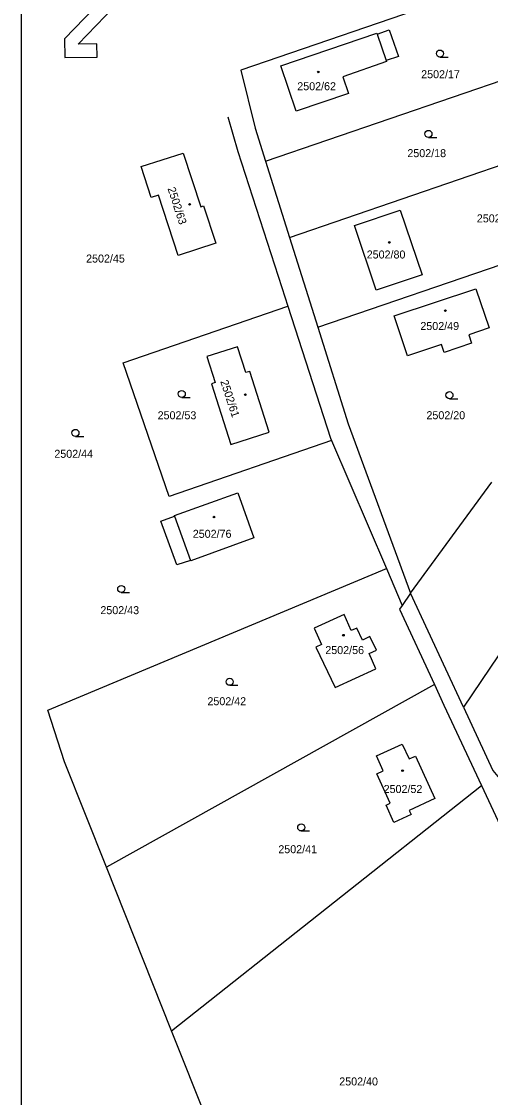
# Model space of a CAD drawing. Extents: x -558358 to -557517, y -1073785 to -1073189.
# Drawn here: x -558357.5 to -558258, y -1073555.9 to -1073327.3 of the extents above; entities that cross this region are included whole.
import ezdxf

# ---------------------------------------------------------------- set-up
doc = ezdxf.new("R2010")
doc.units = 0
for name, color, linetype in [('Hranice parcel', 7, 'Continuous'), ('Parcelní čísla', 7, 'Continuous'), ('Vnitřní kresba', 7, 'Continuous'), ('Vrstva 1', 7, 'Continuous'), ('Značky budov', 7, 'Continuous'), ('Značky kultur', 7, 'Continuous')]:
    doc.layers.add(name, color=color, linetype=linetype)

msp = doc.modelspace()

# ---------------------------------------------------------------- linework, layer by layer
at = {"layer": 'Hranice parcel'}
for p, q in [((-558245.27, -1073315.03), (-558311.02, -1073337.58)), ((-558305.76, -1073356.92), (-558240.15, -1073334.41)), ((-558300.65, -1073373.14), (-558235.73, -1073350.87)), ((-558305.76, -1073356.92), (-558300.65, -1073373.14)), ((-558294.64, -1073392.22), (-558230.35, -1073370.17)), ((-558300.65, -1073373.14), (-558294.64, -1073392.22)), ((-558302.31, -1073383.75), (-558301.02, -1073387.75)), ((-558335.97, -1073399.79), (-558301.02, -1073387.75)), ((-558294.64, -1073392.22), (-558288.18, -1073412.71)), ((-558326.19, -1073428.15), (-558335.97, -1073399.79)), ((-558288.18, -1073412.71), (-558274.97, -1073448.74)), ((-558291.74, -1073416.28), (-558326.19, -1073428.15)), ((-558291.74, -1073416.28), (-558280.07, -1073443.5)), ((-558274.97, -1073448.74), (-558257.7, -1073425.14)), ((-558351.92, -1073473.58), (-558280.07, -1073443.5)), ((-558280.07, -1073443.5), (-558276.72, -1073451.31)), ((-558274.97, -1073448.74), (-558276.72, -1073451.31)), ((-558263.73, -1073472.95), (-558274.97, -1073448.74)), ((-558269.87, -1073468.15), (-558339.52, -1073506.95)), ((-558325.69, -1073541.72), (-558259.89, -1073489.61)), ((-558325.69, -1073541.72), (-558339.52, -1073506.95)), ((-558314.35, -1073570.26), (-558325.69, -1073541.72))]:
    msp.add_line(p, q, dxfattribs=at)
for points in [[(-558302.49, -1073336.69), (-558282.13, -1073329.71), (-558282.06, -1073329.92), (-558279.49, -1073329.04), (-558277.55, -1073334.7), (-558280.12, -1073335.56), (-558280.04, -1073335.79), (-558289.36, -1073338.99), (-558288.15, -1073342.54), (-558299.21, -1073346.34), (-558302.49, -1073336.69)], [(-558311.02, -1073337.58), (-558307.96, -1073349.92), (-558305.76, -1073356.92)], [(-558313.78, -1073347.52), (-558311.65, -1073354.86), (-558302.31, -1073383.75)], [(-558329.99, -1073364.63), (-558332.12, -1073358.09), (-558323.21, -1073355.2), (-558319.51, -1073366.6), (-558318.91, -1073366.43), (-558316.33, -1073374.39), (-558324.28, -1073376.97), (-558328.43, -1073364.14), (-558329.99, -1073364.63)], [(-558282.25, -1073384.34), (-558286.86, -1073370.59), (-558277.14, -1073367.32), (-558272.5, -1073381.07), (-558282.25, -1073384.34)], [(-558278.42, -1073389.81), (-558261.13, -1073384.05), (-558258.31, -1073392.37), (-558262.58, -1073393.82), (-558262, -1073395.6), (-558267.81, -1073397.55), (-558268.37, -1073395.87), (-558275.59, -1073398.26), (-558278.42, -1073389.81)], [(-558301.02, -1073387.75), (-558291.95, -1073415.8), (-558291.74, -1073416.28)], [(-558309.9, -1073401.85), (-558311.67, -1073396.36), (-558318.22, -1073398.44), (-558316.44, -1073403.96), (-558317.23, -1073404.23), (-558313.09, -1073417.12), (-558304.96, -1073414.53), (-558309.1, -1073401.61), (-558309.9, -1073401.85)], [(-558321.61, -1073441.85), (-558321.65, -1073441.75), (-558324.57, -1073442.7), (-558327.97, -1073433.39), (-558325.04, -1073432.33), (-558325.07, -1073432.22), (-558311.66, -1073427.42), (-558308.26, -1073436.97), (-558321.61, -1073441.85)], [(-558252.58, -1073492.61), (-558249.44, -1073487.92), (-558239.75, -1073494.46), (-558236.97, -1073490.34), (-558223.28, -1073470.09), (-558220.49, -1073465.96), (-558246.94, -1073448.09), (-558263.73, -1073472.95)], [(-558287.54, -1073456.66), (-558289.07, -1073453.28), (-558295.45, -1073456.18), (-558293.85, -1073459.61), (-558295.04, -1073460.19), (-558290.99, -1073468.78), (-558282.34, -1073464.77), (-558283.75, -1073461.57), (-558282.21, -1073460.84), (-558283.59, -1073457.95), (-558285.18, -1073458.67), (-558286.36, -1073456.15), (-558287.54, -1073456.66)], [(-558276.72, -1073451.31), (-558277.28, -1073452.14), (-558269.87, -1073468.15)], [(-558269.87, -1073468.15), (-558267.87, -1073472.49), (-558259.89, -1073489.61)], [(-558339.52, -1073506.95), (-558348.44, -1073484.55), (-558351.92, -1073473.58)], [(-558263.73, -1073472.95), (-558257.48, -1073486.4), (-558252.9, -1073491.92), (-558252.58, -1073492.61)], [(-558280.17, -1073493.77), (-558279.26, -1073493.36), (-558282.12, -1073487.08), (-558280.77, -1073486.48), (-558282.2, -1073483.29), (-558276.72, -1073480.79), (-558275.28, -1073483.95), (-558273.92, -1073483.36), (-558269.81, -1073492.38), (-558275.26, -1073494.86), (-558274.85, -1073495.76), (-558278.51, -1073497.42), (-558280.17, -1073493.77)], [(-558259.89, -1073489.61), (-558244.04, -1073523.6), (-558239.03, -1073535.96)]]:
    msp.add_lwpolyline(points, dxfattribs=at)
at = {"layer": 'Vnitřní kresba'}
for p, q in [((-558282.06, -1073329.92), (-558280.12, -1073335.56)), ((-558325.04, -1073432.33), (-558321.65, -1073441.75))]:
    msp.add_line(p, q, dxfattribs=at)
at = {"layer": 'Vrstva 1'}
for p, q in [((-558357.53, -1073784.09), (-558357.53, -1073190.09)), ((-558280.86, -1073260.92), (-558348.4, -1073330.92)), ((-558345.54, -1073332.05), (-558278.82, -1073262.89)), ((-558348.4, -1073330.92), (-558348.32, -1073334.93)), ((-558341.53, -1073331.97), (-558345.54, -1073332.05)), ((-558341.48, -1073334.81), (-558341.53, -1073331.97)), ((-558348.32, -1073334.93), (-558341.48, -1073334.81))]:
    msp.add_line(p, q, dxfattribs=at)
at = {"layer": 'Značky budov'}
for centre in [(-558294.55, -1073337.97), (-558321.85, -1073366.12), (-558279.47, -1073374.21), (-558267.57, -1073388.69), (-558310.02, -1073406.56), (-558316.7, -1073432.55), (-558289.2, -1073457.65), (-558276.67, -1073486.42)]:
    msp.add_circle(centre, 0.175, dxfattribs=at)
at = {"layer": 'Značky kultur'}
for p, q in [((-558268.73, -1073334.82), (-558266.98, -1073334.82)), ((-558271.17, -1073351.89), (-558269.42, -1073351.89)), ((-558323.52, -1073407.14), (-558321.77, -1073407.14)), ((-558266.71, -1073407.4), (-558264.96, -1073407.4)), ((-558346.09, -1073415.41), (-558344.34, -1073415.41)), ((-558336.38, -1073448.57), (-558334.63, -1073448.57)), ((-558313.35, -1073468.3), (-558311.6, -1073468.3)), ((-558298.17, -1073499.24), (-558296.42, -1073499.24))]:
    msp.add_line(p, q, dxfattribs=at)
for centre in [(-558268.73, -1073334.07), (-558271.17, -1073351.14), (-558323.52, -1073406.39), (-558266.71, -1073406.65), (-558346.09, -1073414.66), (-558336.38, -1073447.82), (-558313.35, -1073467.55), (-558298.17, -1073498.49)]:
    msp.add_circle(centre, 0.75, dxfattribs=at)

# ---------------------------------------------------------------- texts
at = {"layer": 'Parcelní čísla'}
for s, p in [('2502/17', (-558272.71, -1073339.31)), ('2502/62', (-558299.01, -1073341.86)), ('2502/18', (-558275.64, -1073356.08)), ('2502/19', (-558260.9, -1073369.94)), ('2502/80', (-558284.27, -1073377.61)), ('2502/45', (-558343.83, -1073378.47)), ('2502/49', (-558272.88, -1073392.81)), ('2502/53', (-558328.65, -1073411.77)), ('2502/20', (-558271.59, -1073411.76)), ('2502/44', (-558350.57, -1073419.96)), ('2502/76', (-558321.19, -1073436.96)), ('2502/43', (-558340.8, -1073453.18)), ('2502/56', (-558293.06, -1073461.66)), ('2502/42', (-558318.08, -1073472.53)), ('2502/52', (-558280.68, -1073491.18)), ('2502/41', (-558303.03, -1073503.97)), ('2502/40', (-558290.1, -1073553.31))]:
    msp.add_text(s, height=1.7, dxfattribs=at).set_placement(p)
for s, p in [('2502/63', (-558326.57, -1073362.74)), ('2502/61', (-558315.36, -1073403.73))]:
    msp.add_text(s, height=1.7, rotation=288, dxfattribs=at).set_placement(p)

doc.saveas('drawing.dxf')
